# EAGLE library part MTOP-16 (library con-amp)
AMP connector
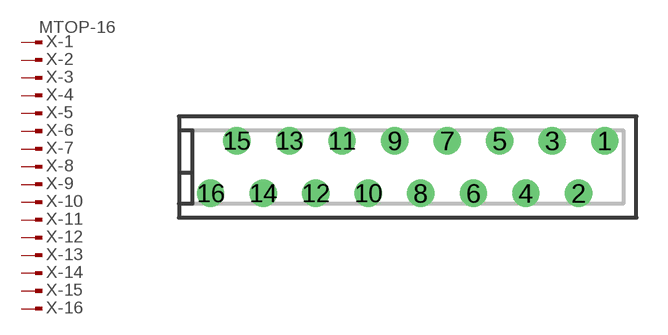
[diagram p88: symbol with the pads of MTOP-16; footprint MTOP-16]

Designator prefix X; gates -1=PIN-MV -2=PIN-M -3=PIN-M -4=PIN-M -5=PIN-M -6=PIN-M -7=PIN-M -8=PIN-M -9=PIN-M -10=PIN-M -11=PIN-M -12=PIN-M -13=PIN-M -14=PIN-M -15=PIN-M -16=PIN-M

## MTOP-16 (OC_FARNELL: unknown; OC_NEWARK: unknown)  [MTOP-16]
1  -1:1  pas
2  -2:1  pas
3  -3:1  pas
4  -4:1  pas
5  -5:1  pas
6  -6:1  pas
7  -7:1  pas
8  -8:1  pas
9  -9:1  pas
10  -10:1  pas
11  -11:1  pas
12  -12:1  pas
13  -13:1  pas
14  -14:1  pas
15  -15:1  pas
16  -16:1  pas

## Footprint MTOP-16 (pad centres in mm)
AMP connector
drill 0.813 round: 1 9.525,1.27; 2 8.255,-1.27; 3 6.985,1.27; 4 5.715,-1.27; 5 4.445,1.27; 6 3.175,-1.27; 7 1.905,1.27; 8 0.635,-1.27; 9 -0.635,1.27; 10 -1.905,-1.27; 11 -3.175,1.27; 12 -4.445,-1.27; 13 -5.715,1.27; 14 -6.985,-1.27; 15 -8.255,1.27; 16 -9.525,-1.27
